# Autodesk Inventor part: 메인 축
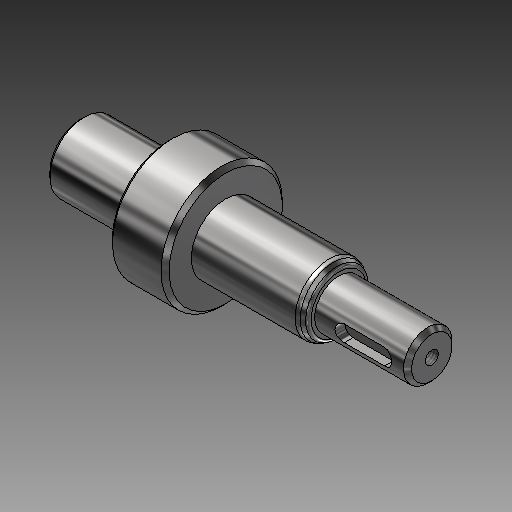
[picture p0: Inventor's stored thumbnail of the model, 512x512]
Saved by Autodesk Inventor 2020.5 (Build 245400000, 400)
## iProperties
Created: 2016-04
Part Number: 메인 축
Document SubType Name: Modeling
Designer: mdu
Density: 7.86 g/cm^3
Mass: 230.24 g
Surface Area: 74.3518 cm^2
Volume: 29.2926 cm^3
Material: 강철, 연강
Appearance: 반광택
Author: mdu
Revision Number: 1
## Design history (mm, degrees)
sketch "스케치1"
  geometry: L1 (10.497, -57.5)-(97.497, -57.5); L2 (10.497, -66)-(32.497, -66); L3 (32.497, -72.5)-(46.5, -72.5); L4 (46.5, -66)-(74.497, -66); L5 (97.497, -63.5)-(97.497, -57.5); L6 (10.497, -66)-(10.497, -57.5); L7 (46.5, -69.749)-(46.5, -45.251) reference; L8 (46.5, -72.5)-(46.5, -66); L9 (32.497, -72.5)-(32.497, -66); L10 (32.497, -35)-(32.497, -80) reference; L11 (97.497, -63.5)-(74.497, -63.5); L12 (74.497, -63.5)-(74.497, -66); 3 further points
  constraints: 20 end point, 4 perpendicular, 3 point on line, 2 parallel, 1 collinear, 1 horizontal, 1 midpoint
  dimensions: "d0" = 17 diameter of L4 L1; "d1" = 30 diameter of L3 L1; "d2" = 22 distance of L2.start L2.end; "d5" = 17 diameter of L2 L1; "d19" = 65 distance between parallel lines of L5 L9; "d21" = 50.99692 distance between parallel lines of L5 L8 (derived); "d22" = 23 distance between parallel lines of L5 L12; "d23" = 12 diameter of L11 L1
revolve "회전1" sketch "스케치1" stored, may be unused: angle "d4" = 90 deg
chamfer "모따기1" distance "d6" = 1; stored, may be unused: second distance "d7" = 2, angle "d8" = 45 deg
node "작업 평면1"
sketch "스케치2"
  geometry: L1 (10.497, -65)-(10.497, -50) reference; L2 (16.997, -55)-(25.997, -55); L3 (25.997, -60)-(16.997, -60); A1 r 2.5 centre (25.997, -57.5) between (25.997, -60) and (25.997, -55); A2 r 2.5 centre (16.997, -57.5) between (16.997, -55) and (16.997, -60); 2 further points
  constraints: 4 end point, 4 point on circle, 4 tangent, 2 centre point, 1 horizontal alignment, 1 midpoint, 1 parallel, 1 perpendicular
  dimensions: "d9" = 5 distance between parallel lines of L3 L2; "d10" = 14 dimension on A1 A2; "d11" = 4 distance edge to line of A2 L1
extrude "돌출1" cut sketch "스케치2" distance "d12" = 3; taper "d13" = 0 deg
node "작업 평면2"
sketch "스케치3"
  geometry: L1 (91.497, -55.5)-(81.497, -55.5); L2 (81.497, -59.5)-(91.497, -59.5); L3 (97.497, -52.5)-(97.497, -62.5) reference; A1 r 2 centre (81.497, -57.5) between (81.497, -55.5) and (81.497, -59.5); A2 r 2 centre (91.497, -57.5) between (91.497, -59.5) and (91.497, -55.5); 4 further points
  constraints: 4 end point, 4 point on circle, 4 tangent, 2 centre point, 2 horizontal, 2 point on line, 1 horizontal alignment, 1 midpoint, 1 vertical alignment
  dimensions: "d32" = 14 dimension on A2 A1; "d34" = 4 distance edge to line of A2 L3; "d35" = 4 distance between parallel lines of L2 L1
extrude "돌출2" cut sketch "스케치3" distance "d16" = 2.5; taper "d17" = 0 deg
sketch "스케치4"
  geometry: L1 (74.497, -50.05)-(72.678, -49); L2 (74.497, -49)-(46.5, -49) reference; L3 (74.497, -49)-(74.497, -66) reference; L4 (74.497, -66)-(46.5, -66) reference; L5 (74.497, -57.5)-(60.711, -57.5); 1 further point
  constraints: 4 end point, 2 point on line, 1 midpoint, 1 parallel
  dimensions: "d24" = 14.9 diameter of L1.start L5; "d26" = 30 deg angle of L2 L1
revolve "회전2" sketch "스케치4" stored, may be unused: angle "d28" = 90 deg
fillet "모깎기1" dims "d29" = 1
fillet "모깎기2" dims "d30" = 2
hole "구멍1" diameter "d38" = 3.242; stored, may be unused: countersink angle "d42" = 90 deg, drill point angle "d44" = 118 deg; dims "d39" = 8, "d40" = 4, "d41" = 2, "d43" = 10, "d45" = 10, "d46" = 10
node "솔리드1"
node "참조4"
node "참조5"
other parameters: "d20" = 6, "d47" = -8.5
